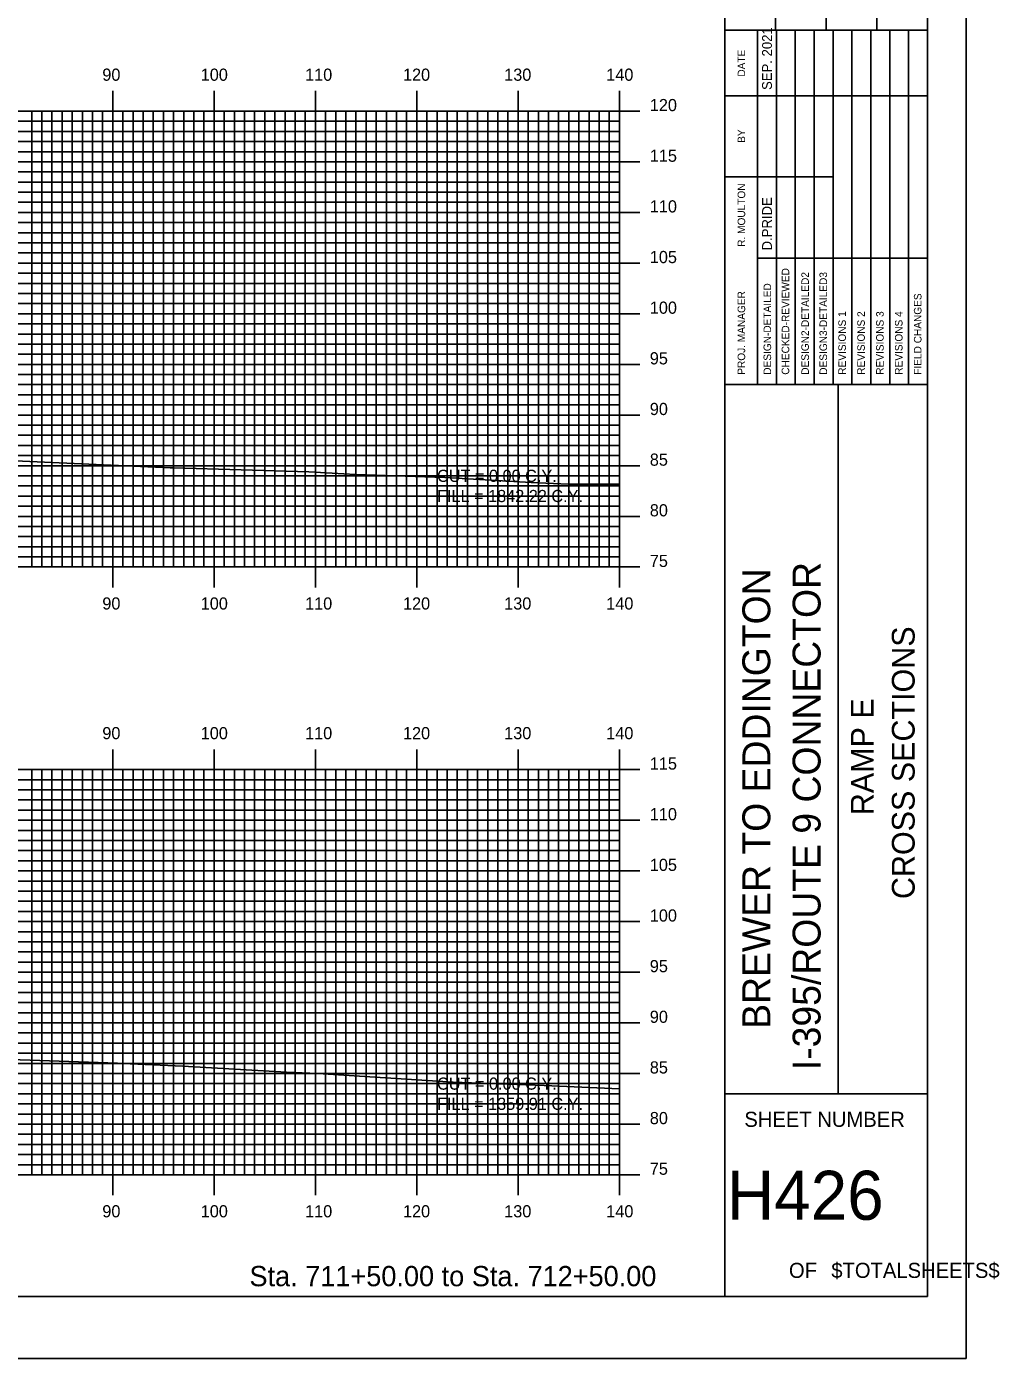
# Model space of a CAD drawing. Extents: x 855297 to 855640, y 364366 to 364586.
# Drawn here: x 855544.3 to 855640.3, y 364365.7 to 364497.1 of the extents above; entities that cross this region are included whole.
import ezdxf

# ---------------------------------------------------------------- set-up
doc = ezdxf.new("R2010")
doc.units = 0
for name, color, linetype in [('BORDER', 7, 'Continuous'), ('D_Text_Standard', 7, 'Continuous'), ('H_V ANNOTATION', 7, 'Continuous'), ('MAJOR', 7, 'Continuous'), ('MINOR', 7, 'Continuous'), ('PLOT BOUNDARY', 7, 'Continuous'), ('S_Roadway_Centerline', 7, 'Continuous')]:
    doc.layers.add(name, color=color, linetype=linetype)

msp = doc.modelspace()

# ---------------------------------------------------------------- linework, layer by layer
at = {"layer": 'BORDER'}
for p, q in [((855613.17, 364371.79), (855613.17, 364581.79)), ((855618.17, 364496.79), (855618.17, 364514.09)), ((855623.17, 364496.79), (855623.17, 364514.09)), ((855628.17, 364496.79), (855628.17, 364514.09)), ((855613.17, 364496.79), (855633.17, 364496.79)), ((855613.17, 364461.79), (855633.17, 364461.79)), ((855624.35, 364391.79), (855624.35, 364461.79)), ((855613.17, 364391.79), (855633.17, 364391.79))]:
    msp.add_line(p, q, dxfattribs=at)
msp.add_lwpolyline([(855313.17, 364371.79), (855633.17, 364371.79), (855633.17, 364581.79), (855313.17, 364581.79)], close=True, dxfattribs=at)
for points in [[(855616.4, 364490.29), (855616.4, 364496.79)], [(855618.26, 364461.8), (855618.26, 364496.79)], [(855620.13, 364496.79), (855620.13, 364461.8)], [(855621.99, 364461.8), (855621.99, 364496.79)], [(855623.85, 364461.8), (855623.85, 364496.79)], [(855625.72, 364461.8), (855625.72, 364496.79)], [(855627.58, 364461.8), (855627.58, 364496.79)], [(855629.45, 364461.8), (855629.45, 364496.79)], [(855631.31, 364461.8), (855631.31, 364496.79)], [(855616.4, 364461.8), (855616.4, 364495.38)], [(855613.17, 364490.29), (855633.17, 364490.29)], [(855613.17, 364482.29), (855616.4, 364482.29)], [(855616.4, 364482.29), (855623.85, 364482.29)], [(855616.4, 364474.29), (855633.17, 364474.29)]]:
    msp.add_lwpolyline(points, dxfattribs=at)
at = {"layer": 'MAJOR'}
for p, q in [((855552.77, 364490.79), (855552.77, 364488.79)), ((855562.77, 364490.79), (855562.77, 364488.79)), ((855572.77, 364490.79), (855572.77, 364488.79)), ((855582.77, 364490.79), (855582.77, 364488.79)), ((855592.77, 364490.79), (855592.77, 364488.79)), ((855602.77, 364490.79), (855602.77, 364488.79)), ((855322.77, 364488.79), (855602.77, 364488.79)), ((855322.77, 364488.79), (855602.77, 364488.79)), ((855552.77, 364443.79), (855552.77, 364488.79)), ((855562.77, 364443.79), (855562.77, 364488.79)), ((855572.77, 364443.79), (855572.77, 364488.79)), ((855582.77, 364443.79), (855582.77, 364488.79)), ((855592.77, 364443.79), (855592.77, 364488.79)), ((855604.77, 364488.79), (855600.77, 364488.79)), ((855602.77, 364443.79), (855602.77, 364488.79)), ((855602.77, 364443.79), (855602.77, 364488.79)), ((855322.77, 364483.79), (855602.77, 364483.79)), ((855604.77, 364483.79), (855600.77, 364483.79)), ((855322.77, 364478.79), (855602.77, 364478.79)), ((855604.77, 364478.79), (855600.77, 364478.79)), ((855322.77, 364473.79), (855602.77, 364473.79)), ((855604.77, 364473.79), (855600.77, 364473.79)), ((855322.77, 364468.79), (855602.77, 364468.79)), ((855604.77, 364468.79), (855600.77, 364468.79)), ((855322.77, 364463.79), (855602.77, 364463.79)), ((855604.77, 364463.79), (855600.77, 364463.79)), ((855322.77, 364458.79), (855602.77, 364458.79)), ((855604.77, 364458.79), (855600.77, 364458.79)), ((855322.77, 364453.79), (855602.77, 364453.79)), ((855604.77, 364453.79), (855600.77, 364453.79)), ((855322.77, 364448.79), (855602.77, 364448.79)), ((855604.77, 364448.79), (855600.77, 364448.79)), ((855322.77, 364443.79), (855602.77, 364443.79)), ((855322.77, 364443.79), (855602.77, 364443.79)), ((855552.77, 364441.78), (855552.77, 364443.79)), ((855562.77, 364441.78), (855562.77, 364443.79)), ((855572.77, 364441.78), (855572.77, 364443.79)), ((855582.77, 364441.78), (855582.77, 364443.79)), ((855592.77, 364441.78), (855592.77, 364443.79)), ((855604.77, 364443.79), (855600.77, 364443.79)), ((855602.77, 364441.78), (855602.77, 364443.79)), ((855552.77, 364425.79), (855552.77, 364423.79)), ((855562.77, 364425.79), (855562.77, 364423.79)), ((855572.77, 364425.79), (855572.77, 364423.79)), ((855582.77, 364425.79), (855582.77, 364423.79)), ((855592.77, 364425.79), (855592.77, 364423.79)), ((855602.77, 364425.79), (855602.77, 364423.79)), ((855322.77, 364423.79), (855602.77, 364423.79)), ((855322.77, 364423.79), (855602.77, 364423.79)), ((855552.77, 364383.79), (855552.77, 364423.79)), ((855562.77, 364383.79), (855562.77, 364423.79)), ((855572.77, 364383.79), (855572.77, 364423.79)), ((855582.77, 364383.79), (855582.77, 364423.79)), ((855592.77, 364383.79), (855592.77, 364423.79)), ((855604.77, 364423.79), (855600.77, 364423.79)), ((855602.77, 364383.79), (855602.77, 364423.79)), ((855602.77, 364383.79), (855602.77, 364423.79)), ((855322.77, 364418.79), (855602.77, 364418.79)), ((855604.77, 364418.79), (855600.77, 364418.79)), ((855322.77, 364413.79), (855602.77, 364413.79)), ((855604.77, 364413.79), (855600.77, 364413.79)), ((855322.77, 364408.79), (855602.77, 364408.79)), ((855604.77, 364408.79), (855600.77, 364408.79)), ((855322.77, 364403.79), (855602.77, 364403.79)), ((855604.77, 364403.79), (855600.77, 364403.79)), ((855322.77, 364398.79), (855602.77, 364398.79)), ((855604.77, 364398.79), (855600.77, 364398.79)), ((855322.77, 364393.79), (855602.77, 364393.79)), ((855604.77, 364393.79), (855600.77, 364393.79)), ((855322.77, 364388.79), (855602.77, 364388.79)), ((855604.77, 364388.79), (855600.77, 364388.79)), ((855322.77, 364383.79), (855602.77, 364383.79)), ((855322.77, 364383.79), (855602.77, 364383.79)), ((855552.77, 364381.78), (855552.77, 364383.79)), ((855562.77, 364381.78), (855562.77, 364383.79)), ((855572.77, 364381.78), (855572.77, 364383.79)), ((855582.77, 364381.78), (855582.77, 364383.79)), ((855592.77, 364381.78), (855592.77, 364383.79)), ((855604.77, 364383.79), (855600.77, 364383.79)), ((855602.77, 364381.78), (855602.77, 364383.79))]:
    msp.add_line(p, q, dxfattribs=at)
at = {"layer": 'MINOR'}
for p, q in [((855544.77, 364443.79), (855544.77, 364488.79)), ((855545.77, 364443.79), (855545.77, 364488.79)), ((855546.77, 364443.79), (855546.77, 364488.79)), ((855547.77, 364443.79), (855547.77, 364488.79)), ((855548.77, 364443.79), (855548.77, 364488.79)), ((855549.77, 364443.79), (855549.77, 364488.79)), ((855550.77, 364443.79), (855550.77, 364488.79)), ((855551.77, 364443.79), (855551.77, 364488.79)), ((855553.77, 364443.79), (855553.77, 364488.79)), ((855554.77, 364443.79), (855554.77, 364488.79)), ((855555.77, 364443.79), (855555.77, 364488.79)), ((855556.77, 364443.79), (855556.77, 364488.79)), ((855557.77, 364443.79), (855557.77, 364488.79)), ((855558.77, 364443.79), (855558.77, 364488.79)), ((855559.77, 364443.79), (855559.77, 364488.79)), ((855560.77, 364443.79), (855560.77, 364488.79)), ((855561.77, 364443.79), (855561.77, 364488.79)), ((855563.77, 364443.79), (855563.77, 364488.79)), ((855564.77, 364443.79), (855564.77, 364488.79)), ((855565.77, 364443.79), (855565.77, 364488.79)), ((855566.77, 364443.79), (855566.77, 364488.79)), ((855567.77, 364443.79), (855567.77, 364488.79)), ((855568.77, 364443.79), (855568.77, 364488.79)), ((855569.77, 364443.79), (855569.77, 364488.79)), ((855570.77, 364443.79), (855570.77, 364488.79)), ((855571.77, 364443.79), (855571.77, 364488.79)), ((855573.77, 364443.79), (855573.77, 364488.79)), ((855574.77, 364443.79), (855574.77, 364488.79)), ((855575.77, 364443.79), (855575.77, 364488.79)), ((855576.77, 364443.79), (855576.77, 364488.79)), ((855577.77, 364443.79), (855577.77, 364488.79)), ((855578.77, 364443.79), (855578.77, 364488.79)), ((855579.77, 364443.79), (855579.77, 364488.79)), ((855580.77, 364443.79), (855580.77, 364488.79)), ((855581.77, 364443.79), (855581.77, 364488.79)), ((855583.77, 364443.79), (855583.77, 364488.79)), ((855584.77, 364443.79), (855584.77, 364488.79)), ((855585.77, 364443.79), (855585.77, 364488.79)), ((855586.77, 364443.79), (855586.77, 364488.79)), ((855587.77, 364443.79), (855587.77, 364488.79)), ((855588.77, 364443.79), (855588.77, 364488.79)), ((855589.77, 364443.79), (855589.77, 364488.79)), ((855590.77, 364443.79), (855590.77, 364488.79)), ((855591.77, 364443.79), (855591.77, 364488.79)), ((855593.77, 364443.79), (855593.77, 364488.79)), ((855594.77, 364443.79), (855594.77, 364488.79)), ((855595.77, 364443.79), (855595.77, 364488.79)), ((855596.77, 364443.79), (855596.77, 364488.79)), ((855597.77, 364443.79), (855597.77, 364488.79)), ((855598.77, 364443.79), (855598.77, 364488.79)), ((855599.77, 364443.79), (855599.77, 364488.79)), ((855600.77, 364443.79), (855600.77, 364488.79)), ((855601.77, 364443.79), (855601.77, 364488.79)), ((855322.77, 364487.79), (855602.77, 364487.79)), ((855602.77, 364487.79), (855600.77, 364487.79)), ((855322.77, 364486.79), (855602.77, 364486.79)), ((855322.77, 364485.79), (855602.77, 364485.79)), ((855602.77, 364486.79), (855600.77, 364486.79)), ((855602.77, 364485.79), (855600.77, 364485.79)), ((855322.77, 364484.79), (855602.77, 364484.79)), ((855602.77, 364484.79), (855600.77, 364484.79)), ((855322.77, 364482.79), (855602.77, 364482.79)), ((855322.77, 364481.79), (855602.77, 364481.79)), ((855602.77, 364482.79), (855600.77, 364482.79)), ((855602.77, 364481.79), (855600.77, 364481.79)), ((855322.77, 364480.79), (855602.77, 364480.79)), ((855602.77, 364480.79), (855600.77, 364480.79)), ((855322.77, 364479.79), (855602.77, 364479.79)), ((855602.77, 364479.79), (855600.77, 364479.79)), ((855322.77, 364477.79), (855602.77, 364477.79)), ((855602.77, 364477.79), (855600.77, 364477.79)), ((855322.77, 364476.79), (855602.77, 364476.79)), ((855602.77, 364476.79), (855600.77, 364476.79)), ((855322.77, 364475.79), (855602.77, 364475.79)), ((855602.77, 364475.79), (855600.77, 364475.79)), ((855322.77, 364474.79), (855602.77, 364474.79)), ((855602.77, 364474.79), (855600.77, 364474.79)), ((855322.77, 364472.79), (855602.77, 364472.79)), ((855602.77, 364472.79), (855600.77, 364472.79)), ((855322.77, 364471.79), (855602.77, 364471.79)), ((855602.77, 364471.79), (855600.77, 364471.79)), ((855322.77, 364470.79), (855602.77, 364470.79)), ((855602.77, 364470.79), (855600.77, 364470.79)), ((855322.77, 364469.79), (855602.77, 364469.79)), ((855602.77, 364469.79), (855600.77, 364469.79)), ((855322.77, 364467.79), (855602.77, 364467.79)), ((855602.77, 364467.79), (855600.77, 364467.79)), ((855322.77, 364466.79), (855602.77, 364466.79)), ((855602.77, 364466.79), (855600.77, 364466.79)), ((855322.77, 364465.79), (855602.77, 364465.79)), ((855322.77, 364464.79), (855602.77, 364464.79)), ((855602.77, 364465.79), (855600.77, 364465.79)), ((855602.77, 364464.79), (855600.77, 364464.79)), ((855322.77, 364462.79), (855602.77, 364462.79)), ((855602.77, 364462.79), (855600.77, 364462.79)), ((855322.77, 364461.79), (855602.77, 364461.79)), ((855322.77, 364460.79), (855602.77, 364460.79)), ((855602.77, 364461.79), (855600.77, 364461.79)), ((855602.77, 364460.79), (855600.77, 364460.79)), ((855322.77, 364459.79), (855602.77, 364459.79)), ((855602.77, 364459.79), (855600.77, 364459.79)), ((855322.77, 364457.79), (855602.77, 364457.79)), ((855322.77, 364456.79), (855602.77, 364456.79)), ((855602.77, 364457.79), (855600.77, 364457.79)), ((855602.77, 364456.79), (855600.77, 364456.79)), ((855322.77, 364455.79), (855602.77, 364455.79)), ((855602.77, 364455.79), (855600.77, 364455.79)), ((855322.77, 364454.79), (855602.77, 364454.79)), ((855602.77, 364454.79), (855600.77, 364454.79)), ((855322.77, 364452.79), (855602.77, 364452.79)), ((855602.77, 364452.79), (855600.77, 364452.79)), ((855322.77, 364451.79), (855602.77, 364451.79)), ((855602.77, 364451.79), (855600.77, 364451.79)), ((855322.77, 364450.79), (855602.77, 364450.79)), ((855602.77, 364450.79), (855600.77, 364450.79)), ((855322.77, 364449.79), (855602.77, 364449.79)), ((855602.77, 364449.79), (855600.77, 364449.79)), ((855322.77, 364447.79), (855602.77, 364447.79)), ((855602.77, 364447.79), (855600.77, 364447.79)), ((855322.77, 364446.79), (855602.77, 364446.79)), ((855602.77, 364446.79), (855600.77, 364446.79)), ((855322.77, 364445.79), (855602.77, 364445.79)), ((855602.77, 364445.79), (855600.77, 364445.79)), ((855322.77, 364444.79), (855602.77, 364444.79)), ((855602.77, 364444.79), (855600.77, 364444.79)), ((855322.77, 364422.79), (855602.77, 364422.79)), ((855544.77, 364383.79), (855544.77, 364423.79)), ((855545.77, 364383.79), (855545.77, 364423.79)), ((855546.77, 364383.79), (855546.77, 364423.79)), ((855547.77, 364383.79), (855547.77, 364423.79)), ((855548.77, 364383.79), (855548.77, 364423.79)), ((855549.77, 364383.79), (855549.77, 364423.79)), ((855550.77, 364383.79), (855550.77, 364423.79)), ((855551.77, 364383.79), (855551.77, 364423.79)), ((855553.77, 364383.79), (855553.77, 364423.79)), ((855554.77, 364383.79), (855554.77, 364423.79)), ((855555.77, 364383.79), (855555.77, 364423.79)), ((855556.77, 364383.79), (855556.77, 364423.79)), ((855557.77, 364383.79), (855557.77, 364423.79)), ((855558.77, 364383.79), (855558.77, 364423.79)), ((855559.77, 364383.79), (855559.77, 364423.79)), ((855560.77, 364383.79), (855560.77, 364423.79)), ((855561.77, 364383.79), (855561.77, 364423.79)), ((855563.77, 364383.79), (855563.77, 364423.79)), ((855564.77, 364383.79), (855564.77, 364423.79)), ((855565.77, 364383.79), (855565.77, 364423.79)), ((855566.77, 364383.79), (855566.77, 364423.79)), ((855567.77, 364383.79), (855567.77, 364423.79)), ((855568.77, 364383.79), (855568.77, 364423.79)), ((855569.77, 364383.79), (855569.77, 364423.79)), ((855570.77, 364383.79), (855570.77, 364423.79)), ((855571.77, 364383.79), (855571.77, 364423.79)), ((855573.77, 364383.79), (855573.77, 364423.79)), ((855574.77, 364383.79), (855574.77, 364423.79)), ((855575.77, 364383.79), (855575.77, 364423.79)), ((855576.77, 364383.79), (855576.77, 364423.79)), ((855577.77, 364383.79), (855577.77, 364423.79)), ((855578.77, 364383.79), (855578.77, 364423.79)), ((855579.77, 364383.79), (855579.77, 364423.79)), ((855580.77, 364383.79), (855580.77, 364423.79)), ((855581.77, 364383.79), (855581.77, 364423.79)), ((855583.77, 364383.79), (855583.77, 364423.79)), ((855584.77, 364383.79), (855584.77, 364423.79)), ((855585.77, 364383.79), (855585.77, 364423.79)), ((855586.77, 364383.79), (855586.77, 364423.79)), ((855587.77, 364383.79), (855587.77, 364423.79)), ((855588.77, 364383.79), (855588.77, 364423.79)), ((855589.77, 364383.79), (855589.77, 364423.79)), ((855590.77, 364383.79), (855590.77, 364423.79)), ((855591.77, 364383.79), (855591.77, 364423.79)), ((855593.77, 364383.79), (855593.77, 364423.79)), ((855594.77, 364383.79), (855594.77, 364423.79)), ((855595.77, 364383.79), (855595.77, 364423.79)), ((855596.77, 364383.79), (855596.77, 364423.79)), ((855597.77, 364383.79), (855597.77, 364423.79)), ((855598.77, 364383.79), (855598.77, 364423.79)), ((855599.77, 364383.79), (855599.77, 364423.79)), ((855600.77, 364383.79), (855600.77, 364423.79)), ((855602.77, 364422.79), (855600.77, 364422.79)), ((855601.77, 364383.79), (855601.77, 364423.79)), ((855322.77, 364421.79), (855602.77, 364421.79)), ((855602.77, 364421.79), (855600.77, 364421.79)), ((855322.77, 364420.79), (855602.77, 364420.79)), ((855602.77, 364420.79), (855600.77, 364420.79)), ((855322.77, 364419.79), (855602.77, 364419.79)), ((855602.77, 364419.79), (855600.77, 364419.79)), ((855322.77, 364417.79), (855602.77, 364417.79)), ((855602.77, 364417.79), (855600.77, 364417.79)), ((855322.77, 364416.79), (855602.77, 364416.79)), ((855602.77, 364416.79), (855600.77, 364416.79)), ((855322.77, 364415.79), (855602.77, 364415.79)), ((855322.77, 364414.79), (855602.77, 364414.79)), ((855602.77, 364415.79), (855600.77, 364415.79)), ((855602.77, 364414.79), (855600.77, 364414.79)), ((855322.77, 364412.79), (855602.77, 364412.79)), ((855602.77, 364412.79), (855600.77, 364412.79)), ((855322.77, 364411.79), (855602.77, 364411.79)), ((855322.77, 364410.79), (855602.77, 364410.79)), ((855602.77, 364411.79), (855600.77, 364411.79)), ((855602.77, 364410.79), (855600.77, 364410.79)), ((855322.77, 364409.79), (855602.77, 364409.79)), ((855602.77, 364409.79), (855600.77, 364409.79)), ((855322.77, 364407.79), (855602.77, 364407.79)), ((855322.77, 364406.79), (855602.77, 364406.79)), ((855602.77, 364407.79), (855600.77, 364407.79)), ((855602.77, 364406.79), (855600.77, 364406.79)), ((855322.77, 364405.79), (855602.77, 364405.79)), ((855602.77, 364405.79), (855600.77, 364405.79)), ((855322.77, 364404.79), (855602.77, 364404.79)), ((855602.77, 364404.79), (855600.77, 364404.79)), ((855322.77, 364402.79), (855602.77, 364402.79)), ((855322.77, 364401.79), (855602.77, 364401.79)), ((855602.77, 364402.79), (855600.77, 364402.79)), ((855602.77, 364401.79), (855600.77, 364401.79)), ((855322.77, 364400.79), (855602.77, 364400.79)), ((855602.77, 364400.79), (855600.77, 364400.79)), ((855322.77, 364399.79), (855602.77, 364399.79)), ((855602.77, 364399.79), (855600.77, 364399.79)), ((855322.77, 364397.79), (855602.77, 364397.79)), ((855602.77, 364397.79), (855600.77, 364397.79)), ((855322.77, 364396.79), (855602.77, 364396.79)), ((855602.77, 364396.79), (855600.77, 364396.79)), ((855322.77, 364395.79), (855602.77, 364395.79)), ((855602.77, 364395.79), (855600.77, 364395.79)), ((855322.77, 364394.79), (855602.77, 364394.79)), ((855602.77, 364394.79), (855600.77, 364394.79)), ((855322.77, 364392.79), (855602.77, 364392.79)), ((855602.77, 364392.79), (855600.77, 364392.79)), ((855322.77, 364391.79), (855602.77, 364391.79)), ((855602.77, 364391.79), (855600.77, 364391.79)), ((855322.77, 364390.79), (855602.77, 364390.79)), ((855322.77, 364389.79), (855602.77, 364389.79)), ((855602.77, 364390.79), (855600.77, 364390.79)), ((855602.77, 364389.79), (855600.77, 364389.79)), ((855322.77, 364387.79), (855602.77, 364387.79)), ((855602.77, 364387.79), (855600.77, 364387.79)), ((855322.77, 364386.79), (855602.77, 364386.79)), ((855322.77, 364385.79), (855602.77, 364385.79)), ((855602.77, 364386.79), (855600.77, 364386.79)), ((855602.77, 364385.79), (855600.77, 364385.79)), ((855322.77, 364384.79), (855602.77, 364384.79)), ((855602.77, 364384.79), (855600.77, 364384.79))]:
    msp.add_line(p, q, dxfattribs=at)
at = {"layer": 'PLOT BOUNDARY'}
msp.add_lwpolyline([(855296.98, 364365.67), (855636.98, 364365.67), (855636.98, 364585.67), (855296.98, 364585.67)], close=True, dxfattribs=at)
at = {"layer": 'S_Roadway_Centerline'}
for points in [[(855440.56, 364458.03), (855452.48, 364457.55), (855458.28, 364457.53), (855470.98, 364456.71), (855473.03, 364456.62), (855488.52, 364456.21), (855496.57, 364455.98), (855505.95, 364455.71), (855517.72, 364455.43), (855521.47, 364455.37), (855523.61, 364455.27), (855534.94, 364454.75), (855541.62, 364454.34), (855558.44, 364453.58), (855558.56, 364453.58), (855558.61, 364453.58), (855558.76, 364453.57), (855572.13, 364453.19), (855576.71, 364452.91), (855585.53, 364452.63), (855594.06, 364452.13), (855597.72, 364451.97), (855602.77, 364451.96)], [(855441.38, 364399.78), (855451.75, 364399.5), (855457.89, 364399.2), (855468.91, 364399.12), (855484.04, 364398.04), (855485.55, 364397.92), (855498.6, 364397.72), (855502.2, 364397.62), (855512.9, 364397.11), (855519.86, 364396.56), (855527.26, 364396.18), (855536.84, 364395.55), (855540.72, 364395.24), (855553.23, 364394.81), (855554.48, 364394.76), (855559.67, 364394.5), (855569.9, 364393.92), (855573, 364393.78), (855586.35, 364392.94), (855595.35, 364392.6), (855602.77, 364392.29)]]:
    msp.add_lwpolyline(points, dxfattribs=at)

# ---------------------------------------------------------------- texts
at = {"layer": 'BORDER'}
for s, height, p in [('SEP. 2021', 0.969, (855617.82, 364490.88)), ('DATE', 0.743, (855615.18, 364492.2)), ('BY', 0.743, (855615.18, 364485.66)), ('R. MOULTON', 0.745, (855615.18, 364475.4)), ('D.PRIDE', 0.969, (855617.82, 364475.04)), ('CHECKED-REVIEWED', 0.7455, (855619.53, 364462.77)), ('DESIGN2-DETAILED2', 0.7455, (855621.47, 364462.77)), ('DESIGN3-DETAILED3', 0.7455, (855623.26, 364462.77)), ('DESIGN-DETAILED', 0.7455, (855617.74, 364462.77)), ('PROJ. MANAGER', 0.7455, (855615.18, 364462.77)), ('FIELD CHANGES', 0.7455, (855632.58, 364462.77)), ('REVISIONS 1', 0.7455, (855625.12, 364462.77)), ('REVISIONS 2', 0.7455, (855626.99, 364462.77)), ('REVISIONS 3', 0.7455, (855628.85, 364462.77)), ('REVISIONS 4', 0.7455, (855630.71, 364462.77)), ('I-395/ROUTE 9 CONNECTOR', 2.7557, (855622.62, 364394.12)), ('BREWER TO EDDINGTON', 2.7557, (855617.66, 364398.2)), ('CROSS SECTIONS', 2.25, (855631.91, 364411.01)), ('RAMP E', 2.25, (855627.86, 364419.29))]:
    msp.add_text(s, height=height, rotation=90, dxfattribs=at).set_placement(p)
for s, height, p in [('SHEET NUMBER', 1.4905, (855615.1, 364388.52)), ('H426', 4.839, (855613.38, 364379.35)), ('$TOTALSHEETS$', 1.4905, (855623.68, 364373.61)), ('OF', 1.491, (855619.5, 364373.61))]:
    msp.add_text(s, height=height, dxfattribs=at).set_placement(p)
at = {"layer": 'D_Text_Standard'}
for s, p in [('CUT = 0.00 C.Y.', (855584.77, 364452.19)), ('FILL = 1842.22 C.Y.', (855584.77, 364450.2)), ('CUT = 0.00 C.Y.', (855584.77, 364392.19)), ('FILL = 1359.91 C.Y.', (855584.77, 364390.2))]:
    msp.add_text(s, height=1.2, dxfattribs=at).set_placement(p)
at = {"layer": 'H_V ANNOTATION'}
for s, height, p in [('90', 1.2, (855551.74, 364491.79)), ('100', 1.2, (855561.45, 364491.79)), ('110', 1.2, (855571.75, 364491.79)), ('120', 1.2, (855581.41, 364491.79)), ('130', 1.2, (855591.4, 364491.79)), ('140', 1.2, (855601.47, 364491.79)), ('120', 1.2, (855605.77, 364488.79)), ('115', 1.2, (855605.77, 364483.79)), ('110', 1.2, (855605.77, 364478.79)), ('105', 1.2, (855605.77, 364473.79)), ('100', 1.2, (855605.77, 364468.79)), ('95', 1.2, (855605.77, 364463.79)), ('90', 1.2, (855605.77, 364458.79)), ('85', 1.2, (855605.77, 364453.79)), ('80', 1.2, (855605.77, 364448.79)), ('75', 1.2, (855605.77, 364443.79)), ('90', 1.2, (855551.74, 364439.59)), ('100', 1.2, (855561.45, 364439.59)), ('110', 1.2, (855571.75, 364439.59)), ('120', 1.2, (855581.41, 364439.59)), ('130', 1.2, (855591.4, 364439.59)), ('140', 1.2, (855601.47, 364439.59)), ('90', 1.2, (855551.74, 364426.79)), ('100', 1.2, (855561.45, 364426.79)), ('110', 1.2, (855571.75, 364426.79)), ('120', 1.2, (855581.41, 364426.79)), ('130', 1.2, (855591.4, 364426.79)), ('140', 1.2, (855601.47, 364426.79)), ('115', 1.2, (855605.77, 364423.79)), ('110', 1.2, (855605.77, 364418.79)), ('105', 1.2, (855605.77, 364413.79)), ('100', 1.2, (855605.77, 364408.79)), ('95', 1.2, (855605.77, 364403.79)), ('90', 1.2, (855605.77, 364398.79)), ('85', 1.2, (855605.77, 364393.79)), ('80', 1.2, (855605.77, 364388.79)), ('75', 1.2, (855605.77, 364383.79)), ('90', 1.2, (855551.74, 364379.59)), ('100', 1.2, (855561.45, 364379.59)), ('110', 1.2, (855571.75, 364379.59)), ('120', 1.2, (855581.41, 364379.59)), ('130', 1.2, (855591.4, 364379.59)), ('140', 1.2, (855601.47, 364379.59)), ('Sta. 711+50.00 to Sta. 712+50.00', 2.0004, (855566.26, 364372.79))]:
    msp.add_text(s, height=height, dxfattribs=at).set_placement(p)

doc.saveas('drawing.dxf')
